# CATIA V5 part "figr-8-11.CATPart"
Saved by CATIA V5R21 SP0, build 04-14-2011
Part number: Part2
Bounding box of the stored display mesh (mm): x -37.886 to 37.886, y -61.415 to 61.415, z 29 to 58
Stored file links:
  D:\CATIA V5R21 E-RESOURCES\CATIA-V5R21\catia-v5r21-prt\c08-catia-v5r20-prt\c08-catia-v5r21-figr-8-11.CATPart
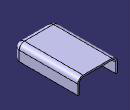
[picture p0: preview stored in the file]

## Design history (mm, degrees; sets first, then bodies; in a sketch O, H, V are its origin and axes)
Body1 (main body)
  Sketch1 on xy-plane, origin (0, 0, 0), H (1, 0, 0), V (0, 1, 0)
    line L1 (37.8862, 61.4155) -> (37.8862, -61.4155)
    line L2 (37.8862, -61.4155) -> (-37.8862, -61.4155)
    line L3 (-37.8862, -61.4155) -> (-37.8862, 61.4155)
    line L4 (-37.8862, 61.4155) -> (37.8862, 61.4155)
    vertical: L1 V, L3 V
    horizontal: L2 H, L4 H
    equidistance: L1 L3 O, L2 L4 O
  Pad1: profile Sketch1, direction (0, 0, 1), length 29
  Fillet1: radius 10, on edge [face of Pad1 | face of Pad1] (x5)
  Shell1: ExtOffset 0, Face (face of Pad1; face of Pad1), IntOffset 3
  Symmetry1: ToTransfor Shell1, Reference face of Pad1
